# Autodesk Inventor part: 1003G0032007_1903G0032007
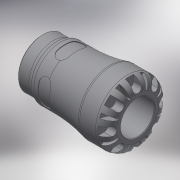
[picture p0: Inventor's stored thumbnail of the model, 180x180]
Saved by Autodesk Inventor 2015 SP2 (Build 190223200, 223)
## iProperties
Created: 2016-12
Part Number: 1003G0032007_1903G0032007
Material: Generic
Description: PLASSON FEMALE ADAPTOR 32X3/4" SERIES 1
Document SubType Name: Modeling
Designer: KIM
Mass: 664.223 g
Surface Area: 733.008 cm^2
Volume: 474.445 cm^3
Density: 1 g/cm^3
Appearance: Default
Author: KIM
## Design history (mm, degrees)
derived "1003G.ipt"
feature "Solid1::1003G.ipt"
tag "TaggingFeature1"
body "Solid1"
other parameters: "d0" = 76, "d1" = 22.68, "d2" = 32, "d4" = 58, "d6" = 54, "d8" = 49.3, "d13" = 7.2, "d14" = 7.2, "d15" = 0, "d17" = 360 deg, "d19" = 8 deg, "d20" = 0.64, "d21" = 0.64, "d22" = 8 deg, "d24" = 0, "d26" = 360 deg, "d32" = 5.8, "d33" = 5.8, "d39" = 0.72351, "d42" = 24.117, "d43" = 45.24, "d46" = 2.66667, "d47" = 12, "d48" = 22.91115, "d50" = 3.3, "d51" = 0.58, "d54" = 11.2, "d55" = 7.04, "d57" = 14.112, "d58" = 0, "d68" = 360 deg, "d72" = 0.64, "d74" = 0, "d76" = 9.52, "d_" = 32, "E_" = 58, "H_" = 76, "l_" = 54, "G_" = 24.117, "l_2" = 12, "d9" = 9, "d11" = 58
